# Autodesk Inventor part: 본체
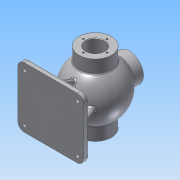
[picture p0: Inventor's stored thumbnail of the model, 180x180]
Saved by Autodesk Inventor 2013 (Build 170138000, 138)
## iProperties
Created: 2018-06
Part Number: 본체
Material: 알루미늄 6061
Document SubType Name: Modeling
Designer: Administrator
Mass: 1509.57 g
Surface Area: 1153.7 cm^2
Volume: 557.037 cm^3
Density: 2.71 g/cm^3
Author: Administrator
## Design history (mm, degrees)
sketch "스케치1"
  geometry: L1 (0, 53)-(0, -53); A1 r 53 centre (0, 0) between (0, -53) and (0, 53); 2 further points
  constraints: 2 coincident, 2 end point, 2 point on circle, 1 centre point, 1 midpoint, 1 vertical
  dimensions: "d0" = 106 distance of L1.start L1.end
revolve "회전1" sketch "스케치1" stored, may be unused: angle "d3" = 90 deg
sketch "스케치2"
  geometry: L1 (0, 43)-(0, -43); A1 r 43 centre (0, 0) between (0, -43) and (0, 43); 2 further points
  constraints: 2 coincident, 2 end point, 2 point on circle, 1 centre point, 1 midpoint, 1 vertical
  dimensions: "d4" = 86 distance of L1.start L1.end
revolve "회전2" sketch "스케치2" stored, may be unused: angle "d7" = 90 deg
node "작업 평면1"
sketch "스케치3"
  geometry: C1 r 31 at (0, 0); 1 further point
  constraints: 1 centre point, 1 coincident
  dimensions: "d9" = 62 diameter of C1
extrude "돌출1" join sketch "스케치3" stored distance "d10" = 10; taper "d11" = 0 deg
node "작업 평면2"
sketch "스케치6"
  geometry: C1 r 31 at (0, 0); 1 further point
  constraints: 1 centre point, 1 coincident
  dimensions: "d27" = 62 diameter of C1
extrude "돌출3" join sketch "스케치6" stored distance "d28" = 10; taper "d29" = 0 deg
sketch "스케치7"
  geometry: C1 r 31 at (0, 0) reference; C2 r 17.5 at (0, 0)
  constraints: 1 centre point, 1 coincident
  dimensions: "d30" = 35 diameter of C2
extrude "돌출4" cut sketch "스케치7" stored distance "d31" = 10; taper "d32" = 0 deg
node "작업 평면3"
sketch "스케치10"
  geometry: C1 r 18.5 at (0, 0); 1 further point
  constraints: 1 centre point, 1 coincident
  dimensions: "d37" = 37 diameter of C1
extrude "돌출6" cut sketch "스케치10" distance "d38" = 1.75; taper "d39" = 0 deg
node "작업 평면4"
sketch "스케치11"
  geometry: C1 r 27 at (0, 0); 1 further point
  constraints: 1 centre point, 1 coincident
  dimensions: "d41" = 54 diameter of C1
extrude "돌출7" join sketch "스케치11" stored distance "d42" = 1.5; taper "d43" = 0 deg
sketch "스케치12"
  geometry: C1 r 17.5 at (0, 0) reference; C2 r 31 at (0, 0) reference; 1 further point
  constraints: 1 vertical alignment
  dimensions: "d44" = 22.5 distance of point (0, 22.5) C2.centre
hole "구멍2" sketch "스케치12" at (0, 22.5) diameter "d45" = 3.242; stored, may be unused: countersink angle "d49" = 90 deg, drill point angle "d51" = 118 deg; dims "d46" = 12, "d47" = 4, "d48" = 2, "d50" = 15
sketch "스케치13"
  geometry: C1 r 17.5 at (0, 0) reference; 1 further point
  constraints: 1 vertical alignment
  dimensions: "d55" = 24 distance of point (0, 24) C1.centre
hole "구멍3" sketch "스케치13" at (0, 24) diameter "d56" = 3.242; stored, may be unused: countersink angle "d60" = 90 deg, drill point angle "d62" = 118 deg; dims "d57" = 16, "d58" = 4, "d59" = 2, "d61" = 19
sketch "스케치14"
  geometry: C1 r 27 at (0, 0) reference; 1 further point
  constraints: 1 vertical alignment
  dimensions: "d66" = 20 distance of C1.centre point (0, 20)
hole "구멍4" sketch "스케치14" at (0, 20) diameter "d67" = 3.242; stored, may be unused: countersink angle "d71" = 90 deg, drill point angle "d73" = 118 deg; dims "d68" = 9, "d69" = 4, "d70" = 2, "d72" = 11
sketch "스케치15"
  geometry: C1 r 27 at (0, 0) reference; C2 r 13 at (0, 0)
  constraints: 1 centre point, 1 coincident
  dimensions: "d77" = 26 diameter of C2
extrude "돌출8" cut sketch "스케치15" stored distance "d78" = 1.5; taper "d79" = 0 deg
node "작업 평면5"
sketch "스케치16"
  geometry: L1 (-62.5, 57.5)-(62.5, 57.5); L2 (62.5, 57.5)-(62.5, -57.5); L3 (62.5, -57.5)-(-62.5, -57.5); L4 (-62.5, -57.5)-(-62.5, 57.5); L5 (-62.5, 57.5)-(62.5, -57.5); L6 (62.5, 57.5)-(-62.5, -57.5); 1 further point
  constraints: 12 end point, 2 midpoint, 2 parallel, 1 horizontal, 1 perpendicular
  dimensions: "d81" = 125 distance of L2.end L3.end; "d82" = 115 distance of L1.end L2.end
extrude "돌출9" join sketch "스케치16" distance "d83" = 10; taper "d84" = 0 deg
fillet "모깎기1" dims "d85" = 12
hole "구멍5" diameter "d88" = 8; stored, may be unused: countersink angle "d92" = 90 deg, drill point angle "d94" = 0 deg; dims "d86" = 10, "d87" = 10, "d89" = 9, "d90" = 12, "d91" = 3, "d93" = 11
hole "구멍6" diameter "d97" = 8; stored, may be unused: countersink angle "d101" = 90 deg, drill point angle "d103" = 0 deg; dims "d95" = 10, "d96" = 10, "d98" = 9, "d99" = 12, "d100" = 3, "d102" = 11
hole "구멍7" diameter "d106" = 8; stored, may be unused: countersink angle "d110" = 90 deg, drill point angle "d112" = 0 deg; dims "d104" = 10, "d105" = 10, "d107" = 9, "d108" = 12, "d109" = 3, "d111" = 11
hole "구멍8" diameter "d115" = 8; stored, may be unused: countersink angle "d119" = 90 deg, drill point angle "d121" = 0 deg; dims "d113" = 10, "d114" = 10, "d116" = 9, "d117" = 12, "d118" = 3, "d120" = 11
sketch "스케치17"
  geometry: L1 (-4, -4)-(4, -4); L2 (4, -4)-(4, 4); L3 (4, 4)-(-4, 4); L4 (-4, 4)-(-4, -4); L5 (-4, -4)-(4, 4); L6 (4, -4)-(-4, 4); 1 further point
  constraints: 12 end point, 2 midpoint, 2 parallel, 1 horizontal, 1 perpendicular
  dimensions: "d122" = 8 distance of L3.end L2.end; "d123" = 8 distance of L2.end L1.end
extrude "돌출10" join sketch "스케치17" stored distance "d124" = 10; taper "d125" = 0 deg
sketch "스케치18"
  geometry: L1 (-52.5, -75)-(-42.226, -49.571); L2 (-62.5, -75)-(-62.5, -85) reference; L3 (-56.5, -75)-(-44.5, -75) reference; L4 (-62.5, -75)-(-50.5, -75) reference; 1 further point
  constraints: 2 end point, 1 point on line
  dimensions: "d126" = 10 distance from line of L1.start L2; "d127" = 112 deg angle of L1 L4
feature "리브1" sketch "스케치18" dims "d128" = 1, "d129" = 8, "d130" = 0, "d131" = 0, "d132" = 1, "d133" = 1
sketch "스케치19"
  geometry: L1 (-75, -47.5)-(-48.113, -36.637); L2 (-75, -57.5)-(-85, -57.5) reference; L3 (-75, -39.5)-(-75, -51.5) reference; L4 (-75, -45.5)-(-75, -57.5) reference; 1 further point
  constraints: 2 end point, 1 point on line
  dimensions: "d134" = 10 distance from line of L2 L1.start; "d135" = 112 deg angle of L4 L1
feature "리브2" sketch "스케치19" dims "d136" = 1, "d137" = 8, "d138" = 0, "d139" = 0, "d140" = 1, "d141" = 1
chamfer "모따기1" distance "d142" = 1; stored, may be unused: second distance "d143" = 2, angle "d144" = 45 deg
fillet "모깎기2" dims "d145" = 3
fillet "모깎기3" dims "d146" = 3
node "작업 평면8"
sketch "스케치21"
  geometry: L1 (0, -27)-(0, 27) reference; 2 further points
  constraints: 1 other
  dimensions: "d151" = 10 distance from line of point (10, 0) L1; "d152" = 27 vertical distance of point (10, 0) L1.start
feature "엠보싱2" sketch "스케치21" dims "d153" = 0.5, "d154" = 0
node "솔리드1"
pattern_circular "원형 패턴2" dims angle "d53" = 360 deg
pattern_circular "원형 패턴3" dims angle "d64" = 360 deg
pattern_circular "원형 패턴4" dims angle "d75" = 360 deg
mirror "대칭1"
mirror "대칭2"
other parameters: "d8" = 68, "d26" = -68, "d36" = -16, "d40" = 65, "d80" = -85
